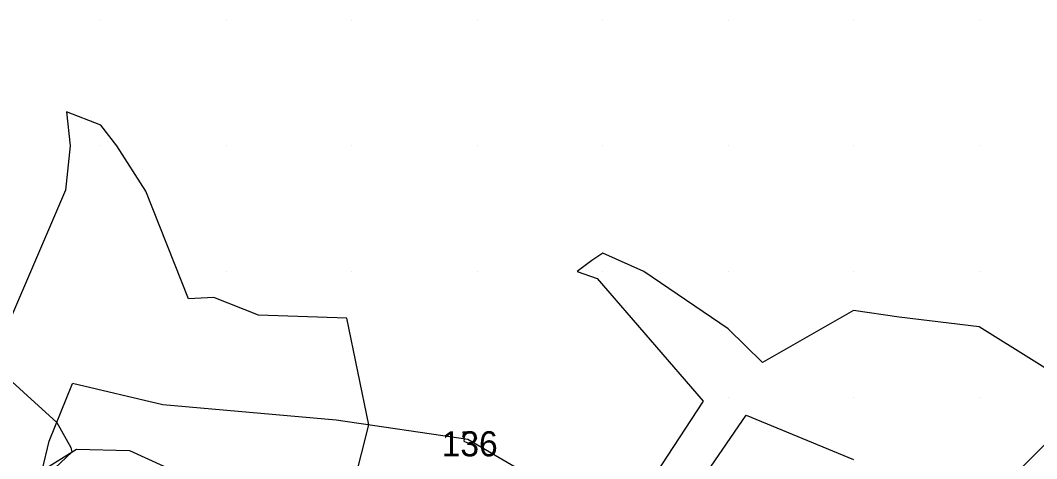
# Model space of a CAD drawing. Extents: x 2354170 to 2357230, y 866100 to 868290.
# Drawn here: x 2354433.6 to 2354514.6, y 867865.1 to 867900 of the extents above; entities that cross this region are included whole.
import ezdxf

# ---------------------------------------------------------------- set-up
doc = ezdxf.new("R2010")
doc.units = 0
for name, color, linetype in [('Default', 7, 'Continuous'), ('Exist DTM QL2 LIDAR Elevation Point', 7, 'Continuous'), ('PH Exist DTM Breakline', 7, 'Continuous')]:
    doc.layers.add(name, color=color, linetype=linetype)

msp = doc.modelspace()

# ---------------------------------------------------------------- linework, layer by layer
at = {"layer": 'Default'}
for points in [[(2354460.166, 867863.192), (2354461.316, 867867.8), (2354459.58, 867876.305), (2354452.535, 867876.551), (2354448.973, 867877.943), (2354446.966, 867877.842), (2354443.563, 867886.423), (2354441.247, 867890.021), (2354439.965, 867891.67), (2354437.245, 867892.741), (2354437.529, 867890.021), (2354437.149, 867886.51), (2354431.623, 867873.663)], [(2354509.966, 867861), (2354518.958, 867870.021), (2354509.966, 867875.604), (2354503.605, 867876.382), (2354499.965, 867876.916), (2354492.711, 867872.766), (2354489.965, 867875.454), (2354483.247, 867880.021), (2354479.965, 867881.486), (2354479.099, 867880.887), (2354477.935, 867880.021), (2354479.516, 867879.461), (2354487.973, 867869.695), (2354481.338, 867859.561)], [(2354431.13, 867872.822), (2354436.457, 867868), (2354437.589, 867866.011), (2354437.648, 867865.641), (2354435.872, 867863.948), (2354435.699, 867861.901), (2354438.387, 867858.277), (2354449.85, 867852.107), (2354455.494, 867849.202), (2354467.454, 867842.804), (2354468.18, 867842.431), (2354477.1, 867837.96), (2354477.283, 867837.87), (2354483.401, 867834.738), (2354503.557, 867824.831), (2354506.897, 867822.949), (2354508.345, 867822.189), (2354512.613, 867819.987), (2354533.335, 867809.09)], [(2354484.846, 867859.025), (2354491.402, 867868.584), (2354499.965, 867865.06)], [(2354469.379, 867866.299), (2354469.677, 867866.369), (2354469.924, 867866.747), (2354469.609, 867867.111), (2354469.258, 867867.235), (2354468.819, 867867.22), (2354468.93, 867866.676), (2354468.887, 867866.505), (2354469.379, 867866.299)]]:
    msp.add_lwpolyline(points, dxfattribs=at)
at = {"layer": 'Exist DTM QL2 LIDAR Elevation Point'}
for p, q in [((2354439.965, 867900.021), (2354439.965, 867900.021)), ((2354449.965, 867900.021), (2354449.965, 867900.021)), ((2354459.965, 867900.021), (2354459.965, 867900.021)), ((2354469.965, 867900.021), (2354469.965, 867900.021)), ((2354479.965, 867900.021), (2354479.965, 867900.021)), ((2354489.965, 867900.021), (2354489.965, 867900.021)), ((2354499.965, 867900.021), (2354499.965, 867900.021)), ((2354509.966, 867900.021), (2354509.966, 867900.021)), ((2354439.965, 867890.021), (2354439.965, 867890.021)), ((2354449.965, 867890.021), (2354449.965, 867890.021)), ((2354459.965, 867890.021), (2354459.965, 867890.021)), ((2354469.965, 867890.021), (2354469.965, 867890.021)), ((2354479.965, 867890.021), (2354479.965, 867890.021)), ((2354489.965, 867890.021), (2354489.965, 867890.021)), ((2354499.965, 867890.021), (2354499.965, 867890.021)), ((2354509.966, 867890.021), (2354509.966, 867890.021)), ((2354449.965, 867880.021), (2354449.965, 867880.021)), ((2354459.965, 867880.021), (2354459.965, 867880.021)), ((2354469.965, 867880.021), (2354469.965, 867880.021)), ((2354479.965, 867880.021), (2354479.965, 867880.021)), ((2354489.965, 867880.021), (2354489.965, 867880.021)), ((2354499.965, 867880.021), (2354499.965, 867880.021)), ((2354509.966, 867880.021), (2354509.966, 867880.021)), ((2354489.965, 867870.021), (2354489.965, 867870.021)), ((2354499.965, 867870.021), (2354499.965, 867870.021)), ((2354509.966, 867870.021), (2354509.966, 867870.021))]:
    msp.add_line(p, q, dxfattribs=at)
at = {"layer": 'PH Exist DTM Breakline'}
for points in [[(2354435.112, 867852.761), (2354434.665, 867854.221), (2354434.282, 867855.909), (2354433.787, 867858.128), (2354434.075, 867859.764), (2354434.63, 867861.981), (2354435.294, 867864.185), (2354435.862, 867866.511), (2354437.701, 867871.111)], [(2354565.456, 867811.382), (2354557.252, 867819.525), (2354550.188, 867824.946), (2354539.393, 867831.074), (2354526.857, 867839.168), (2354518.872, 867841.415), (2354508.732, 867844.964), (2354495, 867850.508), (2354482.519, 867858.871), (2354469.225, 867866.633), (2354458.737, 867868.181), (2354444.901, 867869.415), (2354437.701, 867871.111)], [(2354435.294, 867864.185), (2354438.036, 867865.881), (2354442.242, 867865.77), (2354453.484, 867860.653), (2354477.905, 867847.808), (2354492.941, 867838.78), (2354508.515, 867829.877), (2354520.499, 867824.135), (2354532.212, 867819.082)]]:
    msp.add_lwpolyline(points, dxfattribs=at)

# ---------------------------------------------------------------- texts
at = {"layer": 'Default'}
msp.add_text('136', height=2, dxfattribs=at).set_placement((2354467.135, 867865.299))

doc.saveas('drawing.dxf')
